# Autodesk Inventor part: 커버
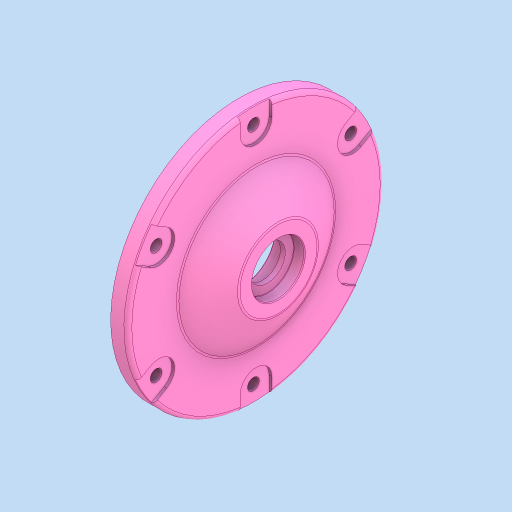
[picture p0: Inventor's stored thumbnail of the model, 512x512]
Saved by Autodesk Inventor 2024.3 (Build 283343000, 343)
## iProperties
Created: 2025-11
Part Number: 커버
Material: 알루미늄 6061
Document SubType Name: Modeling
Designer: PC2-02
Density: 2.7 g/cm^3
Appearance: 기본값
Author: jhkim
Sending System: Autodesk Inventor 2026
Preprocessor: ST-DEVELOPER v20.1
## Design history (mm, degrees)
node "커버1"
node "솔리드2"
node "솔리드1"
